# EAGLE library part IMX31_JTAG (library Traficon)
CONNECTOR
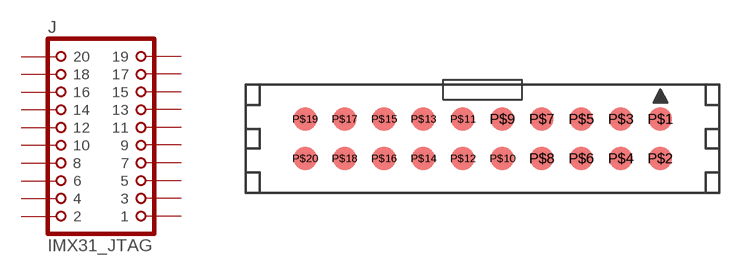
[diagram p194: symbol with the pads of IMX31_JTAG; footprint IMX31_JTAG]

Designator prefix J

## IMX31_JTAG  [IMX31_JTAG]
P$1  1  pas
P$2  2  pas
P$3  3  pas
P$4  4  pas
P$5  5  pas
P$6  6  pas
P$7  7  pas
P$8  8  pas
P$9  9  pas
P$10  10  pas
P$11  11  pas
P$12  12  pas
P$13  13  pas
P$14  14  pas
P$15  15  pas
P$16  16  pas
P$17  17  pas
P$18  18  pas
P$19  19  pas
P$20  20  pas

## Footprint IMX31_JTAG (pad centres in mm)
CONNECTOR
smd 1.5 x 1.5: P$1 11.43,1.27; P$2 11.43,-1.27; P$3 8.89,1.27; P$4 8.89,-1.27; P$5 6.35,1.27; P$6 6.35,-1.27; P$7 3.81,1.27; P$8 3.81,-1.27; P$9 1.27,1.27; P$10 1.27,-1.27; P$11 -1.27,1.27; P$12 -1.27,-1.27; P$13 -3.81,1.27; P$14 -3.81,-1.27; P$15 -6.35,1.27; P$16 -6.35,-1.27; P$17 -8.89,1.27; P$18 -8.89,-1.27; P$19 -11.43,1.27; P$20 -11.43,-1.27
